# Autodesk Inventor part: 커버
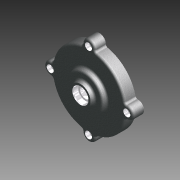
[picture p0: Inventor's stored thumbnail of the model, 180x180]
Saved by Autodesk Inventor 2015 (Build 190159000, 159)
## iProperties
Created: 2012-05
Part Number: 커버
Document SubType Name: 모델링
Designer: SeoGD™
Material: 알루미늄 6061
Appearance: 알루미늄 캐스트
Mass: 195.931 g
Surface Area: 278.607 cm^2
Volume: 72.5671 cm^3
Density: 2.7 g/cm^3
변환 표준: STEP AP214IS
파일 이름: C:\Users\SeoGD\Desktop\?쒗뿕\而ㅻ쾭-1.stp
전처리기: Build: 253, Release: 2010 SP1 - Date: Wed 07/29/2009
전송 단위: 밀리미터
불확실성: 0.01
Author: SeoGD™
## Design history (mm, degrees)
sketch "스케치1"
  geometry: L1 (0, 0)-(0, 26); L2 (50, 0)-(50, 15); L3 (50, 15)-(25, 15); L4 (25, 15)-(25, 21); L5 (25, 21)-(15, 21); L6 (15, 21)-(13.66, 26); L7 (13.66, 26)-(10, 26); L8 (50, 0)-(45, 0); L9 (45, 0)-(45, 10); L10 (45, 10)-(14.5, 10); L11 (14.5, 10)-(13.266, 3); L12 (13.266, 3)-(11, 3); L13 (11, 3)-(11, 16); L14 (11, 16)-(7.5, 16); L15 (7.5, 16)-(7.5, 19); L16 (7.5, 19)-(10, 19); L17 (10, 19)-(10, 26)
  constraints: 34 end point, 10 parallel, 2 perpendicular, 2 point on line, 1 vertical
  dimensions: "d11" = 100 diameter of L2 L1; "d12" = 22 diameter of L13 L1; "d13" = 90 diameter of L9 L1; "d14" = 15 distance between parallel lines of L3 L8; "d15" = 10 distance between parallel lines of L8 L10; "d16" = 29 diameter of L10.end L1; "d17" = 100 deg angle of L11 L10; "d18" = 7 distance between parallel lines of L12 L10; "d19" = 13 distance between parallel lines of L14 L12; "d20" = 3 distance between parallel lines of L16 L14; "d21" = 15 diameter of L15 L1; "d22" = 20 diameter of L17 L1; "d23" = 30 diameter of L5.end L1; "d24" = 6 distance between parallel lines of L5 L3; "d25" = 50 diameter of L4 L1; "d26" = 105 deg angle of L5 L6; "d50" = 26 distance of L1.start L1.end
revolve "회전1" sketch "스케치1" stored, may be unused: angle "d27" = 90 deg
sketch "스케치2" dims "d29" = 104
  geometry: A1 r 8.5 centre (0, 52) between (8.074, 49.344) and (-8.074, 49.344); A2 r 50 centre (0, 0) between (-8.074, 49.344) and (8.074, 49.344) reference; 2 further points
  constraints: 4 point on circle, 2 vertical alignment, 1 centre point, 1 coincident, 2 other
  dimensions: "d28" = 17 diameter of A1
extrude "돌출1" join sketch "스케치2" stored distance "d30" = 10; taper "d31" = 0 deg
fillet "모깎기3" dims "d32" = 3
fillet "모깎기4" dims "d45" = 3, "d46" = 0.2
chamfer "모따기1" distance "d47" = 1; stored, may be unused: second distance "d48" = 2, angle "d49" = 45 deg
hole "구멍2" diameter "d38" = 5.5; stored, may be unused: countersink angle "d42" = 90 deg, drill point angle "d44" = 118 deg; dims "d36" = 10, "d37" = 10, "d39" = 6, "d40" = 9.5, "d41" = 5.4, "d43" = 8
node "솔리드1"
node "솔리드 본체"
node "곡면 본체"
pattern_circular "원형 패턴1" dims angle "d34" = 360 deg
pattern_circular "원형 패턴2" dims angle "d52" = 360 deg
node "솔리드2"
